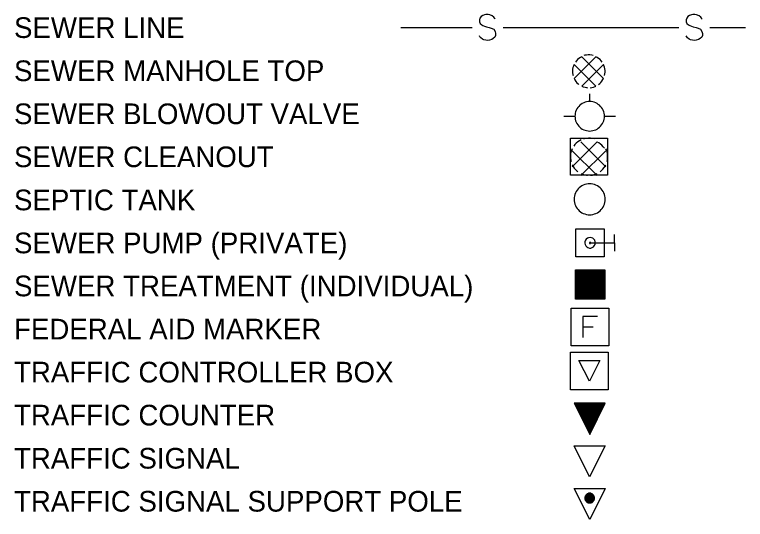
# Model space of a CAD drawing. Extents: x -1.93 to 2.83, y -1.79 to 1.85.
# Drawn here: x 0.5149 to 0.7611, y 1.312 to 1.4822 of the extents above; entities that cross this region are included whole.
import ezdxf

# ---------------------------------------------------------------- set-up
doc = ezdxf.new("R2010")
doc.units = 0
doc.layers.add('Legend', color=7, linetype='Continuous')

msp = doc.modelspace()

# ---------------------------------------------------------------- linework, layer by layer
at = {"layer": 'Legend'}
for p, q in [((0.64504, 1.47783), (0.669, 1.47783)), ((0.67946, 1.47783), (0.73866, 1.47783)), ((0.74912, 1.47783), (0.76108, 1.47783))]:
    msp.add_line(p, q, dxfattribs=at)
for points in [[(0.67678, 1.48062), (0.67671, 1.4809), (0.67637, 1.48131), (0.67582, 1.48179), (0.675, 1.48213), (0.67438, 1.4822), (0.67369, 1.4822), (0.67321, 1.48213), (0.6726, 1.48193), (0.67205, 1.48158), (0.67164, 1.48104), (0.6715, 1.48042), (0.6715, 1.4798), (0.6717, 1.47925), (0.67225, 1.47877), (0.67266, 1.4785), (0.67321, 1.47829), (0.67383, 1.47809), (0.67479, 1.47788), (0.67548, 1.47768), (0.6763, 1.47727), (0.67678, 1.47651), (0.67692, 1.47583), (0.67692, 1.47521), (0.67671, 1.47459), (0.67616, 1.47411), (0.67561, 1.47377), (0.67486, 1.47356), (0.67431, 1.47349), (0.67362, 1.47356), (0.67294, 1.4737), (0.67246, 1.47397), (0.67191, 1.47439), (0.67164, 1.47466), (0.6715, 1.47507)], [(0.74644, 1.48062), (0.74638, 1.4809), (0.74603, 1.48131), (0.74548, 1.48179), (0.74466, 1.48213), (0.74404, 1.4822), (0.74336, 1.4822), (0.74288, 1.48213), (0.74226, 1.48193), (0.74171, 1.48158), (0.7413, 1.48104), (0.74116, 1.48042), (0.74116, 1.4798), (0.74137, 1.47925), (0.74192, 1.47877), (0.74233, 1.4785), (0.74288, 1.47829), (0.7435, 1.47809), (0.74446, 1.47788), (0.74514, 1.47768), (0.74596, 1.47727), (0.74644, 1.47651), (0.74658, 1.47583), (0.74658, 1.47521), (0.74638, 1.47459), (0.74583, 1.47411), (0.74528, 1.47377), (0.74452, 1.47356), (0.74398, 1.47349), (0.74329, 1.47356), (0.7426, 1.4737), (0.74212, 1.47397), (0.74158, 1.47439), (0.7413, 1.47466), (0.74116, 1.47507)], [(0.71073, 1.46799), (0.70335, 1.46066)], [(0.70598, 1.46799), (0.70548, 1.4677), (0.70498, 1.46741), (0.70456, 1.46703), (0.70414, 1.46662), (0.70381, 1.46616)], [(0.70593, 1.46799), (0.71331, 1.46066)], [(0.70985, 1.46841), (0.70931, 1.46853), (0.70873, 1.46862), (0.70814, 1.46862), (0.7076, 1.46857), (0.70702, 1.46849), (0.70668, 1.46837)], [(0.71285, 1.46616), (0.71248, 1.46662), (0.7121, 1.46703), (0.71164, 1.46741), (0.71118, 1.46774), (0.71068, 1.46799)], [(0.70339, 1.46541), (0.70314, 1.46487), (0.70298, 1.46432), (0.70289, 1.46378), (0.70285, 1.4632), (0.70285, 1.46262), (0.70293, 1.46203), (0.70302, 1.46162)], [(0.70335, 1.46541), (0.71073, 1.45807)], [(0.71331, 1.46541), (0.70593, 1.45807)], [(0.71364, 1.46166), (0.71377, 1.4622), (0.71381, 1.46278), (0.71381, 1.46337), (0.71373, 1.46391), (0.7136, 1.46449), (0.71343, 1.46503), (0.71327, 1.46541)], [(0.70339, 1.46066), (0.70364, 1.46016), (0.70398, 1.4597), (0.70435, 1.45924), (0.70477, 1.45887), (0.70502, 1.45866)], [(0.71156, 1.45862), (0.71202, 1.45895), (0.71239, 1.45937), (0.71277, 1.45982), (0.7131, 1.46028), (0.71327, 1.46066)], [(0.70598, 1.45807), (0.70648, 1.45787), (0.70706, 1.4577), (0.7076, 1.45762), (0.70789, 1.45757)], [(0.70877, 1.45757), (0.70931, 1.45766), (0.70989, 1.45778), (0.71043, 1.45799), (0.71068, 1.45807)], [(0.7086, 1.45553), (0.7086, 1.45295)], [(0.7086, 1.45291), (0.7081, 1.45287), (0.70756, 1.45278), (0.70706, 1.45266), (0.7066, 1.45249), (0.70614, 1.45224), (0.70568, 1.45195), (0.70527, 1.45162), (0.70493, 1.45124), (0.7046, 1.45087), (0.70431, 1.45041), (0.70406, 1.44995), (0.70389, 1.44945), (0.70377, 1.44895), (0.70368, 1.44845), (0.70364, 1.44795), (0.70368, 1.44741), (0.70377, 1.44691), (0.70389, 1.44641), (0.70406, 1.44591), (0.70431, 1.44545), (0.7046, 1.44503), (0.70493, 1.44462), (0.70527, 1.44424), (0.70568, 1.44391), (0.70614, 1.44362), (0.7066, 1.44341), (0.70706, 1.4432), (0.70756, 1.44308), (0.7081, 1.44299), (0.7086, 1.44295), (0.70914, 1.44299), (0.70964, 1.44308), (0.71014, 1.4432), (0.71064, 1.44341), (0.7111, 1.44362), (0.71152, 1.44391), (0.71193, 1.44424), (0.71231, 1.44462), (0.71264, 1.44503), (0.71289, 1.44545), (0.71314, 1.44591), (0.71335, 1.44641), (0.71348, 1.44691), (0.71356, 1.44741), (0.71356, 1.44795), (0.71356, 1.44845), (0.71348, 1.44895), (0.71335, 1.44945), (0.71314, 1.44995), (0.71289, 1.45041), (0.71264, 1.45087), (0.71231, 1.45124), (0.71193, 1.45162), (0.71152, 1.45195), (0.7111, 1.45224), (0.71064, 1.45249), (0.71014, 1.45266), (0.70964, 1.45278), (0.70914, 1.45287), (0.7086, 1.45291)], [(0.69993, 1.44795), (0.70364, 1.44795)], [(0.7136, 1.44791), (0.71731, 1.44791)], [(0.70214, 1.42803), (0.70214, 1.44057), (0.71468, 1.44057), (0.71468, 1.42803), (0.70214, 1.42803)], [(0.71014, 1.44032), (0.70952, 1.44045), (0.70885, 1.44053), (0.70818, 1.44057), (0.70756, 1.44049), (0.70689, 1.44037), (0.70656, 1.44028)], [(0.71114, 1.43928), (0.70273, 1.43087)], [(0.70573, 1.43995), (0.70514, 1.43966), (0.7046, 1.43928), (0.7041, 1.43882), (0.70364, 1.43837), (0.70327, 1.43782)], [(0.70568, 1.43928), (0.7141, 1.43087)], [(0.71356, 1.43716), (0.71318, 1.43766), (0.71273, 1.43816), (0.71223, 1.43857), (0.71168, 1.43895), (0.71114, 1.43924)], [(0.70277, 1.43699), (0.70252, 1.43641), (0.70231, 1.43578), (0.70218, 1.43512), (0.70214, 1.43445), (0.70218, 1.43382), (0.70227, 1.43316), (0.70235, 1.43266)], [(0.70273, 1.43628), (0.71114, 1.42791)], [(0.7141, 1.43628), (0.70568, 1.42791)], [(0.71448, 1.4327), (0.7146, 1.43337), (0.71468, 1.43399), (0.71468, 1.43466), (0.7146, 1.43532), (0.71448, 1.43595), (0.71427, 1.43657), (0.71406, 1.43699)], [(0.70277, 1.43157), (0.70306, 1.43103), (0.70343, 1.43049), (0.70389, 1.42999), (0.70435, 1.42953), (0.7046, 1.42932)], [(0.7121, 1.42924), (0.7126, 1.42966), (0.7131, 1.43012), (0.71348, 1.43062), (0.71385, 1.43116), (0.71406, 1.43157)], [(0.70573, 1.42866), (0.70631, 1.42837), (0.70693, 1.4282), (0.7076, 1.42807), (0.70793, 1.42803)], [(0.70889, 1.42803), (0.70956, 1.42812), (0.71018, 1.42828), (0.71081, 1.42849), (0.71114, 1.42866)], [(0.7086, 1.41471), (0.70914, 1.41475), (0.70968, 1.41483), (0.71023, 1.415), (0.71073, 1.41517), (0.71123, 1.41542), (0.71168, 1.41571), (0.7121, 1.41608), (0.71252, 1.41646), (0.71285, 1.41687), (0.71314, 1.41733), (0.71339, 1.41783), (0.7136, 1.41833), (0.71373, 1.41887), (0.71381, 1.41942), (0.71385, 1.41996), (0.71381, 1.4205), (0.71373, 1.42104), (0.7136, 1.42158), (0.71339, 1.42208), (0.71314, 1.42254), (0.71285, 1.423), (0.71252, 1.42346), (0.7121, 1.42383), (0.71168, 1.42417), (0.71123, 1.42446), (0.71073, 1.42471), (0.71023, 1.42492), (0.70968, 1.42504), (0.70914, 1.42512), (0.7086, 1.42517), (0.70806, 1.42512), (0.70752, 1.42504), (0.70702, 1.42492), (0.70648, 1.42471), (0.70602, 1.42446), (0.70556, 1.42417), (0.7051, 1.42383), (0.70473, 1.42346), (0.70439, 1.423), (0.7041, 1.42254), (0.70385, 1.42208), (0.70364, 1.42158), (0.70352, 1.42104), (0.70343, 1.4205), (0.70339, 1.41996), (0.70343, 1.41942), (0.70352, 1.41887), (0.70364, 1.41833), (0.70385, 1.41783), (0.7041, 1.41733), (0.70439, 1.41687), (0.70473, 1.41646), (0.7051, 1.41608), (0.70556, 1.41571), (0.70602, 1.41542), (0.70648, 1.41517), (0.70702, 1.415), (0.70752, 1.41483), (0.70806, 1.41475), (0.7086, 1.41471)], [(0.70401, 1.41002), (0.71354, 1.41002), (0.71354, 1.40055), (0.70401, 1.40055), (0.70401, 1.41002)], [(0.70874, 1.40707), (0.70826, 1.407), (0.70785, 1.40679), (0.70744, 1.40645), (0.70716, 1.40611), (0.70703, 1.40563), (0.70703, 1.40515), (0.70709, 1.40467), (0.7073, 1.40426), (0.70764, 1.40391), (0.70805, 1.40364), (0.70853, 1.4035), (0.70901, 1.4035), (0.70949, 1.40364), (0.70991, 1.40391), (0.71018, 1.40426), (0.71045, 1.40467), (0.71052, 1.40515), (0.71052, 1.40563), (0.71032, 1.40611), (0.71004, 1.40645), (0.7097, 1.40679), (0.70922, 1.407), (0.70874, 1.40707)], [(0.70874, 1.40528), (0.71704, 1.40528), (0.71704, 1.4081)], [(0.70874, 1.40549), (0.7086, 1.40542), (0.70853, 1.40528), (0.7086, 1.40508), (0.70874, 1.40508), (0.70895, 1.40508), (0.70895, 1.40528), (0.70895, 1.40542), (0.70874, 1.40549)], [(0.71704, 1.40528), (0.71704, 1.4024)], [(0.70381, 1.38626), (0.70381, 1.39614), (0.71368, 1.39614), (0.71368, 1.38626), (0.70381, 1.38626)], [(0.70423, 1.39614), (0.70423, 1.38626)], [(0.70464, 1.39614), (0.70464, 1.38626)], [(0.70506, 1.39614), (0.70506, 1.38626)], [(0.70543, 1.39614), (0.70543, 1.38626)], [(0.70585, 1.39614), (0.70585, 1.38626)], [(0.70627, 1.39614), (0.70627, 1.38626)], [(0.70668, 1.39614), (0.70668, 1.38626)], [(0.7071, 1.39614), (0.7071, 1.38626)], [(0.70752, 1.39614), (0.70752, 1.38626)], [(0.70793, 1.39614), (0.70793, 1.38626)], [(0.70835, 1.39614), (0.70835, 1.38626)], [(0.70873, 1.39614), (0.70873, 1.38626)], [(0.70914, 1.39614), (0.70914, 1.38626)], [(0.70956, 1.39614), (0.70956, 1.38626)], [(0.70998, 1.39614), (0.70998, 1.38626)], [(0.71039, 1.39614), (0.71039, 1.38626)], [(0.71081, 1.39614), (0.71081, 1.38626)], [(0.71123, 1.39614), (0.71123, 1.38626)], [(0.71164, 1.39614), (0.71164, 1.38626)], [(0.71202, 1.39614), (0.71202, 1.38626)], [(0.71243, 1.39614), (0.71243, 1.38626)], [(0.71285, 1.39614), (0.71285, 1.38626)], [(0.71327, 1.39614), (0.71327, 1.38626)], [(0.70381, 1.39572), (0.71368, 1.39572)], [(0.70381, 1.3953), (0.71368, 1.3953)], [(0.70381, 1.39489), (0.71368, 1.39489)], [(0.70381, 1.39447), (0.71368, 1.39447)], [(0.70381, 1.39409), (0.71368, 1.39409)], [(0.70381, 1.39368), (0.71368, 1.39368)], [(0.70381, 1.39326), (0.71368, 1.39326)], [(0.70381, 1.39284), (0.71368, 1.39284)], [(0.70381, 1.39243), (0.71368, 1.39243)], [(0.70381, 1.39201), (0.71368, 1.39201)], [(0.70381, 1.39159), (0.71368, 1.39159)], [(0.70381, 1.39122), (0.71368, 1.39122)], [(0.70381, 1.3908), (0.71368, 1.3908)], [(0.70381, 1.39039), (0.71368, 1.39039)], [(0.70381, 1.38997), (0.71368, 1.38997)], [(0.70381, 1.38955), (0.71368, 1.38955)], [(0.70381, 1.38914), (0.71368, 1.38914)], [(0.70381, 1.38872), (0.71368, 1.38872)], [(0.70381, 1.3883), (0.71368, 1.3883)], [(0.70381, 1.38793), (0.71368, 1.38793)], [(0.70381, 1.38751), (0.71368, 1.38751)], [(0.70381, 1.38709), (0.71368, 1.38709)], [(0.70381, 1.38668), (0.71368, 1.38668)], [(0.70235, 1.37051), (0.70235, 1.38319), (0.71506, 1.38319), (0.71506, 1.37051), (0.70235, 1.37051)], [(0.71123, 1.38039), (0.70627, 1.38039), (0.70627, 1.37335)], [(0.70627, 1.37697), (0.70977, 1.37697)], [(0.70218, 1.35574), (0.70218, 1.36841), (0.71485, 1.36841), (0.71485, 1.35574), (0.70218, 1.35574)], [(0.70502, 1.36562), (0.71206, 1.36562), (0.70852, 1.35858), (0.70502, 1.36562)], [(0.70339, 1.35116), (0.70864, 1.3407), (0.71385, 1.35116), (0.70339, 1.35116)], [(0.7136, 1.35116), (0.70339, 1.35116)], [(0.71348, 1.35087), (0.70356, 1.35087)], [(0.71335, 1.35062), (0.70368, 1.35062)], [(0.71323, 1.35037), (0.70381, 1.35037)], [(0.71306, 1.35008), (0.70393, 1.35008)], [(0.71293, 1.34983), (0.70406, 1.34983)], [(0.71281, 1.34958), (0.70418, 1.34958)], [(0.71268, 1.34928), (0.70435, 1.34928)], [(0.7126, 1.34903), (0.70448, 1.34903)], [(0.71248, 1.34878), (0.7046, 1.34878)], [(0.71231, 1.34849), (0.70473, 1.34849)], [(0.71218, 1.34828), (0.70485, 1.34828)], [(0.71206, 1.34799), (0.70502, 1.34799)], [(0.71193, 1.34774), (0.70514, 1.34774)], [(0.71181, 1.34749), (0.70527, 1.34749)], [(0.71164, 1.3472), (0.70539, 1.3472)], [(0.71152, 1.34695), (0.70552, 1.34695)], [(0.71139, 1.3467), (0.70564, 1.3467)], [(0.71127, 1.34641), (0.70581, 1.34641)], [(0.71114, 1.34616), (0.70593, 1.34616)], [(0.71102, 1.34591), (0.70606, 1.34591)], [(0.71085, 1.34562), (0.70614, 1.34562)], [(0.71073, 1.34537), (0.70627, 1.34537)], [(0.7106, 1.34512), (0.70639, 1.34512)], [(0.71048, 1.34487), (0.70656, 1.34487)], [(0.71035, 1.34462), (0.70668, 1.34462)], [(0.71023, 1.34437), (0.70681, 1.34437)], [(0.71006, 1.34408), (0.70693, 1.34408)], [(0.70993, 1.34383), (0.70706, 1.34383)], [(0.70981, 1.34358), (0.70718, 1.34358)], [(0.70968, 1.34328), (0.70735, 1.34328)], [(0.70952, 1.34303), (0.70748, 1.34303)], [(0.70939, 1.34274), (0.7076, 1.34274)], [(0.70931, 1.34249), (0.70773, 1.34249)], [(0.70918, 1.34224), (0.70785, 1.34224)], [(0.70906, 1.34195), (0.70802, 1.34195)], [(0.70893, 1.34174), (0.70814, 1.34174)], [(0.70881, 1.34149), (0.70827, 1.34149)], [(0.70864, 1.3412), (0.70839, 1.3412)], [(0.70335, 1.33683), (0.71381, 1.33683), (0.70856, 1.32637), (0.70335, 1.33683)], [(0.70339, 1.32245), (0.71385, 1.32245), (0.70864, 1.31203), (0.70339, 1.32245)], [(0.70864, 1.32087), (0.70843, 1.32087), (0.70827, 1.32083), (0.7081, 1.32078), (0.70793, 1.3207), (0.70781, 1.32066), (0.70764, 1.32053), (0.70752, 1.32045), (0.70739, 1.32033), (0.70731, 1.3202), (0.70718, 1.32003), (0.7071, 1.31987), (0.70706, 1.31974), (0.70702, 1.31958), (0.70698, 1.31937), (0.70698, 1.3192), (0.70698, 1.31903), (0.70702, 1.31887), (0.70706, 1.3187), (0.7071, 1.31853), (0.70718, 1.31841), (0.70731, 1.31824), (0.70739, 1.31812), (0.70752, 1.31799), (0.70764, 1.31787), (0.70781, 1.31778), (0.70793, 1.3177), (0.7081, 1.31766), (0.70827, 1.31762), (0.70843, 1.31758), (0.70864, 1.31758), (0.70881, 1.31758), (0.70898, 1.31762), (0.70914, 1.31766), (0.70931, 1.3177), (0.70943, 1.31778), (0.7096, 1.31787), (0.70973, 1.31799), (0.70985, 1.31812), (0.70993, 1.31824), (0.71006, 1.31841), (0.71014, 1.31853), (0.71018, 1.3187), (0.71023, 1.31887), (0.71027, 1.31903), (0.71027, 1.3192), (0.71027, 1.31937), (0.71023, 1.31958), (0.71018, 1.31974), (0.71014, 1.31987), (0.71006, 1.32003), (0.70993, 1.3202), (0.70985, 1.32033), (0.70973, 1.32045), (0.7096, 1.32053), (0.70943, 1.32066), (0.70931, 1.3207), (0.70914, 1.32078), (0.70898, 1.32083), (0.70881, 1.32087), (0.70864, 1.32087)], [(0.70706, 1.31974), (0.71018, 1.31974)], [(0.70718, 1.31999), (0.71006, 1.31999)], [(0.70735, 1.32024), (0.70989, 1.32024)], [(0.70764, 1.32053), (0.7096, 1.32053)], [(0.70814, 1.32078), (0.7091, 1.32078)], [(0.70698, 1.31945), (0.71027, 1.31945)], [(0.70698, 1.3192), (0.71027, 1.3192)], [(0.70698, 1.31895), (0.71027, 1.31895)], [(0.70706, 1.3187), (0.71018, 1.3187)], [(0.70718, 1.31845), (0.71006, 1.31845)], [(0.70735, 1.3182), (0.70989, 1.3182)], [(0.70764, 1.31791), (0.7096, 1.31791)], [(0.70814, 1.31766), (0.7091, 1.31766)]]:
    msp.add_lwpolyline(points, dxfattribs=at)

# ---------------------------------------------------------------- texts
for s, height, p in [('SEWER LINE', 0.006967, (0.51467, 1.47433)), ('SEWER MANHOLE TOP', 0.0069667, (0.51467, 1.45978)), ('SEWER BLOWOUT VALVE', 0.0069667, (0.51467, 1.44528)), ('SEWER CLEANOUT', 0.0069667, (0.51467, 1.43078)), ('SEPTIC TANK', 0.0069667, (0.51467, 1.41624)), ('SEWER PUMP (PRIVATE)', 0.0069667, (0.51467, 1.40174)), ('SEWER TREATMENT (INDIVIDUAL)', 0.0069667, (0.51467, 1.38724)), ('FEDERAL AID MARKER', 0.0069667, (0.51467, 1.3727)), ('TRAFFIC CONTROLLER BOX', 0.0069667, (0.51467, 1.3582)), ('TRAFFIC COUNTER', 0.0069667, (0.51467, 1.3437)), ('TRAFFIC SIGNAL', 0.0069667, (0.51467, 1.32916)), ('TRAFFIC SIGNAL SUPPORT POLE', 0.0069667, (0.51467, 1.31466))]:
    msp.add_text(s, height=height, dxfattribs=at).set_placement(p)

doc.saveas('drawing.dxf')
